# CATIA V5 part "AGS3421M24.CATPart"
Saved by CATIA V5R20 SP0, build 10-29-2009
Part number: AGS3421M24
Definition: NONE
Nomenclature: AGS3421M24
Source: Unknown
Description: AGS3421M24
Bounding box of the stored display mesh (mm): x -30 to 50, y -21.312 to 21.312, z -17.2 to 17.2
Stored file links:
  C:\Users\Utente\Desktop\IO LAVORO\3D X SITO CF\X SITO\PLASTICA\AGS\AGS3421M24.CATPart
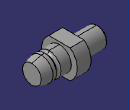
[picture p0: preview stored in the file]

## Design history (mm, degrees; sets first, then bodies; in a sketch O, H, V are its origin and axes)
Body1 "AGS3421M24" (main body)
  Solid1: solid without history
